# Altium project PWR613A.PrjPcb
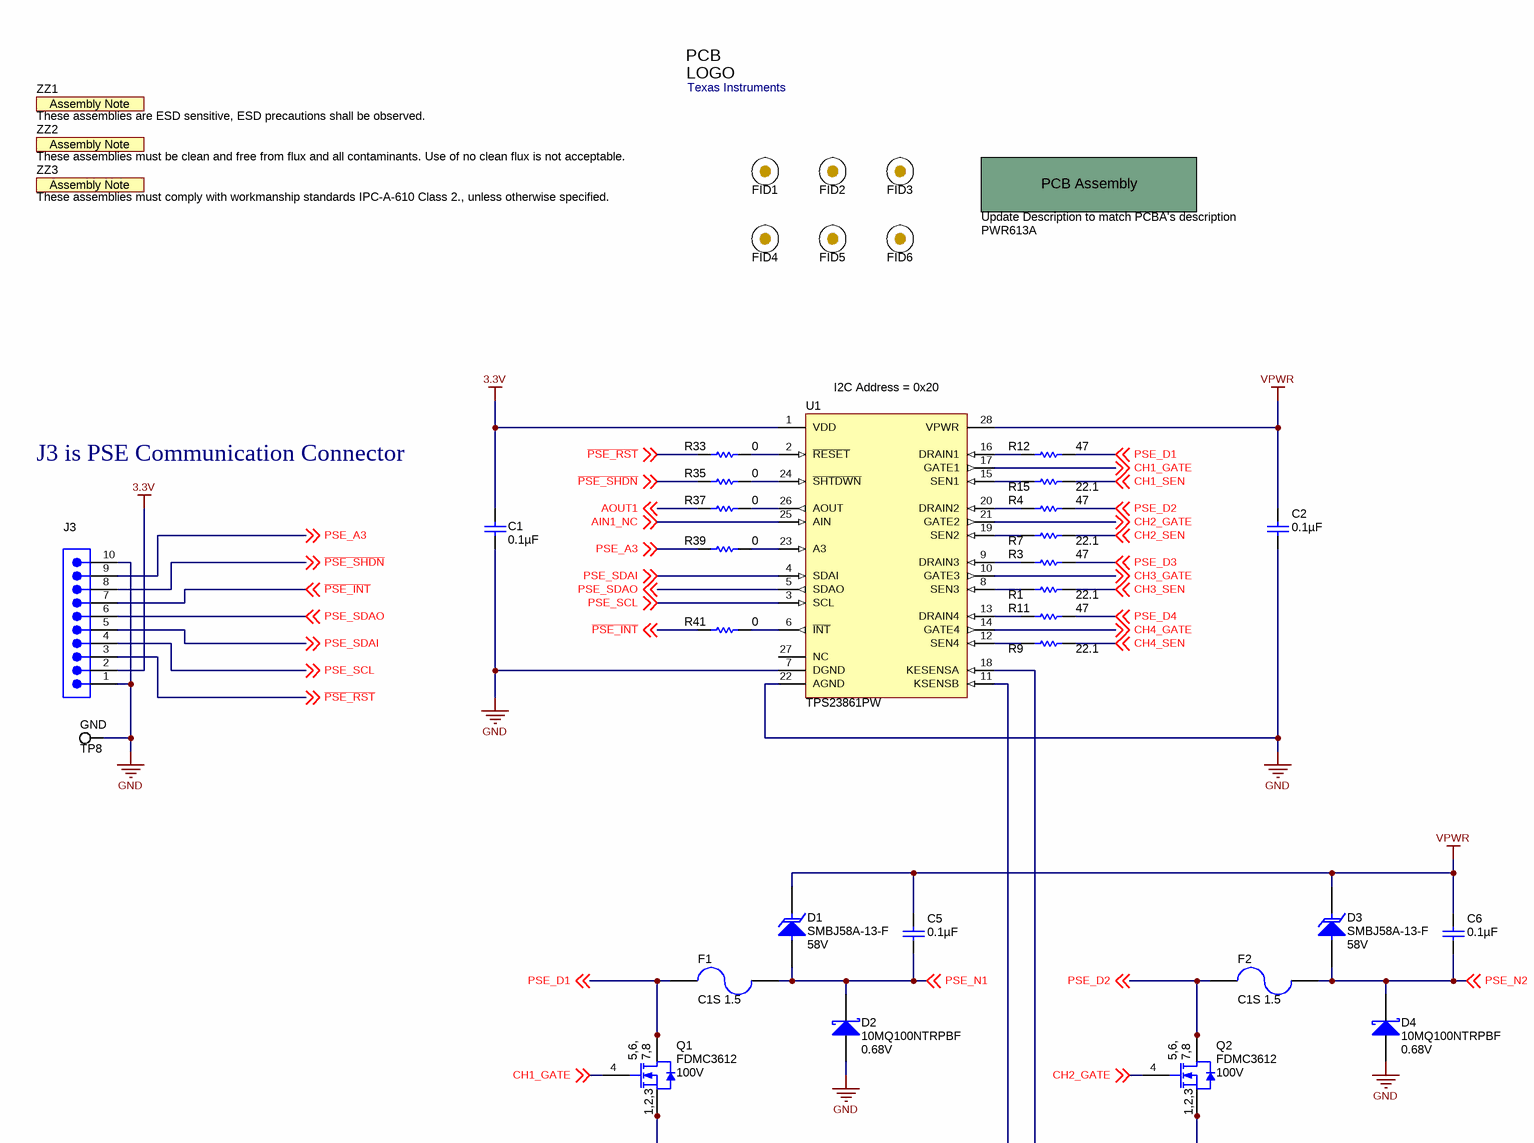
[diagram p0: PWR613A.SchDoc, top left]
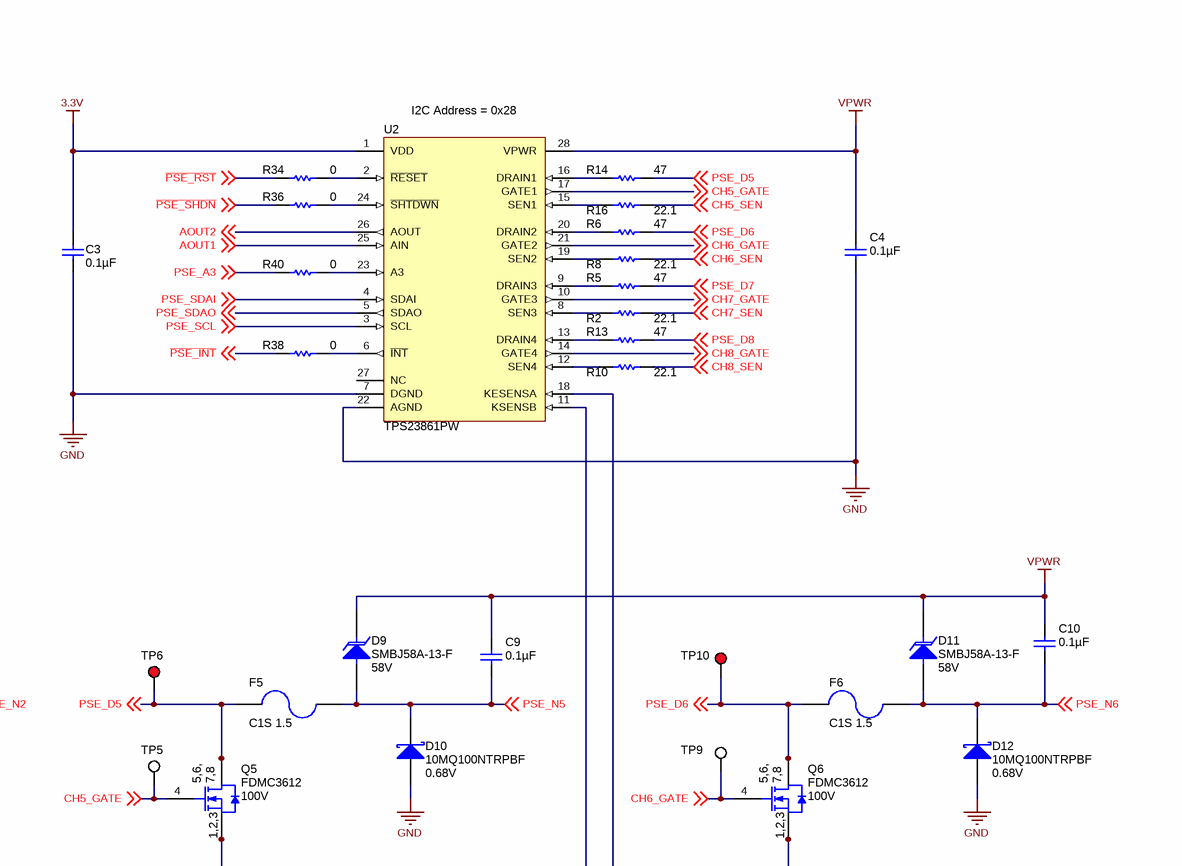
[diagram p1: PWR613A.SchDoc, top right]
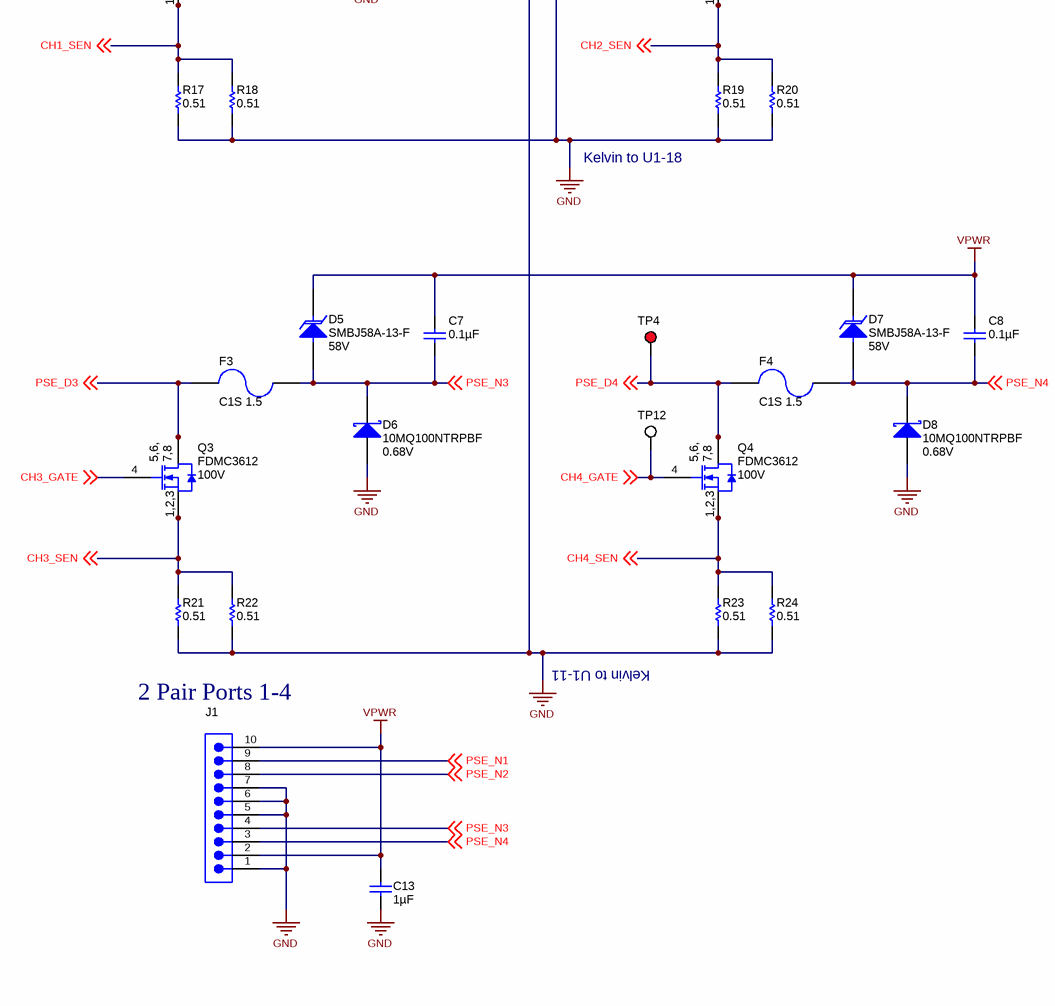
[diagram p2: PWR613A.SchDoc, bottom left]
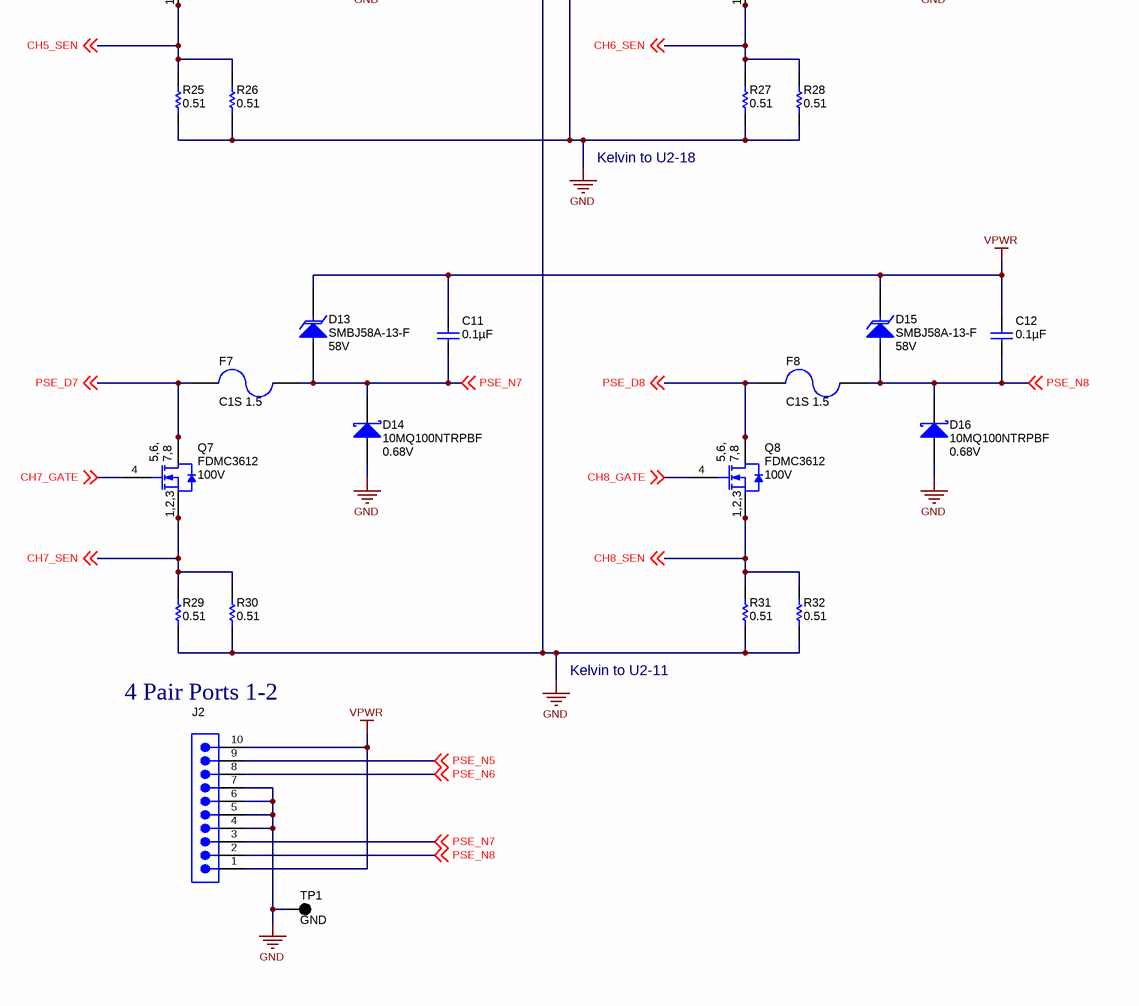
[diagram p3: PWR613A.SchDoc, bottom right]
TechSupport: www.ti.com; SCH_Rev: A; PRJ_Title: TPS23861EVM-613; PRJ_Number: PWR613; PRJ_Engineer: E. Wright; PRJ_Customer: Public Release; PCB_Rev: A; PCB_Layout: E. Wright; CopyrightYear: 2014
1 sheet, 110 parts. Net scope: global (net labels, ports and power ports of the same name join across sheets).
Board file: PWR613A.PcbDoc

## Sheet PWR613A.SchDoc: TPS23861 Daughter Board
size 558 x 431 mm; Engineer: E. Wright; Name: E. Wright

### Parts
!PCBA?  Update Description to match PCBA's description  PartNumber: PWR613A  (mechanical)
C1  ValueDisplayed: 0.1µF  [0603]  (hidden comment: 06035C104KAT2A)
C2  ValueDisplayed: 0.1µF  [0805_HV]  (hidden comment: C2012X7R2A104K)
C3  ValueDisplayed: 0.1µF  [0603]  (hidden comment: 06035C104KAT2A)
C4  ValueDisplayed: 0.1µF  [0805_HV]  (hidden comment: C2012X7R2A104K)
C5  ValueDisplayed: 0.1µF  [0805_HV]  (hidden comment: C2012X7R2A104K)
C6  ValueDisplayed: 0.1µF  [0805_HV]  (hidden comment: C2012X7R2A104K)
C7  ValueDisplayed: 0.1µF  [0805_HV]  (hidden comment: C2012X7R2A104K)
C8  ValueDisplayed: 0.1µF  [0805_HV]  (hidden comment: C2012X7R2A104K)
C9  ValueDisplayed: 0.1µF  [0805_HV]  (hidden comment: C2012X7R2A104K)
C10  ValueDisplayed: 0.1µF  [0805_HV]  (hidden comment: C2012X7R2A104K)
C11  ValueDisplayed: 0.1µF  [0805_HV]  (hidden comment: C2012X7R2A104K)
C12  ValueDisplayed: 0.1µF  [0805_HV]  (hidden comment: C2012X7R2A104K)
C13  ValueDisplayed: 1µF  [1206]  (hidden comment: GRM31CR72A105KA01L)
D1  SMBJ58A-13-F  value 58V  [SMB]
D2  10MQ100NTRPBF  value 0.68V  [SMA]
D3  SMBJ58A-13-F  value 58V  [SMB]
D4  10MQ100NTRPBF  value 0.68V  [SMA]
D5  SMBJ58A-13-F  value 58V  [SMB]
D6  10MQ100NTRPBF  value 0.68V  [SMA]
D7  SMBJ58A-13-F  value 58V  [SMB]
D8  10MQ100NTRPBF  value 0.68V  [SMA]
D9  SMBJ58A-13-F  value 58V  [SMB]
D10  10MQ100NTRPBF  value 0.68V  [SMA]
D11  SMBJ58A-13-F  value 58V  [SMB]
D12  10MQ100NTRPBF  value 0.68V  [SMA]
D13  SMBJ58A-13-F  value 58V  [SMB]
D14  10MQ100NTRPBF  value 0.68V  [SMA]
D15  SMBJ58A-13-F  value 58V  [SMB]
D16  10MQ100NTRPBF  value 0.68V  [SMA]
F1  C1S 1.5  [1206]
F2  C1S 1.5  [1206]
F3  C1S 1.5  [1206]
F4  C1S 1.5  [1206]
F5  C1S 1.5  [1206]
F6  C1S 1.5  [1206]
F7  C1S 1.5  [1206]
F8  C1S 1.5  [1206]
FID1  Fiducial  [Fiducial10-20]  (value not drawn)  (no BOM)
FID2  Fiducial  [Fiducial10-20]  (value not drawn)  (no BOM)
FID3  Fiducial  [Fiducial10-20]  (value not drawn)  (no BOM)
FID4  Fiducial  [Fiducial10-20]  (value not drawn)  (no BOM)
FID5  Fiducial  [Fiducial10-20]  (value not drawn)  (no BOM)
FID6  Fiducial  [Fiducial10-20]  (value not drawn)  (no BOM)
J1  2P4 2P3 2P2 2P1  [TSW-110-07-G-S]  (value not drawn)
J2  Port8&7&6&5  [TSW-110-07-G-S]  (value not drawn)
J3  TSW-110-07-G-S  [TSW-110-07-G-S]  (value not drawn)
Logo1  Texas Instruments  [TI_Symbol_Overlay_Small]  (no BOM)
Q1  FDMC3612  value 100V  [TRANS_Fairchild_MLP08T]
Q2  FDMC3612  value 100V  [TRANS_Fairchild_MLP08T]
Q3  FDMC3612  value 100V  [TRANS_Fairchild_MLP08T]
Q4  FDMC3612  value 100V  [TRANS_Fairchild_MLP08T]
Q5  FDMC3612  value 100V  [TRANS_Fairchild_MLP08T]
Q6  FDMC3612  value 100V  [TRANS_Fairchild_MLP08T]
Q7  FDMC3612  value 100V  [TRANS_Fairchild_MLP08T]
Q8  FDMC3612  value 100V  [TRANS_Fairchild_MLP08T]
R1  value 22.1  [0603]  (hidden comment: CRCW060322R1FKEA)
R2  value 22.1  [0603]  (hidden comment: CRCW060322R1FKEA)
R3  value 47  [0603]  (hidden comment: CRCW060347R0JNEA)
R4  value 47  [0603]  (hidden comment: CRCW060347R0JNEA)
R5  value 47  [0603]  (hidden comment: CRCW060347R0JNEA)
R6  value 47  [0603]  (hidden comment: CRCW060347R0JNEA)
R7  value 22.1  [0603]  (hidden comment: CRCW060322R1FKEA)
R8  value 22.1  [0603]  (hidden comment: CRCW060322R1FKEA)
R9  value 22.1  [0603]  (hidden comment: CRCW060322R1FKEA)
R10  value 22.1  [0603]  (hidden comment: CRCW060322R1FKEA)
R11  value 47  [0603]  (hidden comment: CRCW060347R0JNEA)
R12  value 47  [0603]  (hidden comment: CRCW060347R0JNEA)
R13  value 47  [0603]  (hidden comment: CRCW060347R0JNEA)
R14  value 47  [0603]  (hidden comment: CRCW060347R0JNEA)
R15  value 22.1  [0603]  (hidden comment: CRCW060322R1FKEA)
R16  value 22.1  [0603]  (hidden comment: CRCW060322R1FKEA)
R17  value 0.51  [0805]  (hidden comment: CRM0805-FX-R510ELF)
R18  value 0.51  [0805]  (hidden comment: CRM0805-FX-R510ELF)
R19  value 0.51  [0805]  (hidden comment: CRM0805-FX-R510ELF)
R20  value 0.51  [0805]  (hidden comment: CRM0805-FX-R510ELF)
R21  value 0.51  [0805]  (hidden comment: CRM0805-FX-R510ELF)
R22  value 0.51  [0805]  (hidden comment: CRM0805-FX-R510ELF)
R23  value 0.51  [0805]  (hidden comment: CRM0805-FX-R510ELF)
R24  value 0.51  [0805]  (hidden comment: CRM0805-FX-R510ELF)
R25  value 0.51  [0805]  (hidden comment: CRM0805-FX-R510ELF)
R26  value 0.51  [0805]  (hidden comment: CRM0805-FX-R510ELF)
R27  value 0.51  [0805]  (hidden comment: CRM0805-FX-R510ELF)
R28  value 0.51  [0805]  (hidden comment: CRM0805-FX-R510ELF)
R29  value 0.51  [0805]  (hidden comment: CRM0805-FX-R510ELF)
R30  value 0.51  [0805]  (hidden comment: CRM0805-FX-R510ELF)
R31  value 0.51  [0805]  (hidden comment: CRM0805-FX-R510ELF)
R32  value 0.51  [0805]  (hidden comment: CRM0805-FX-R510ELF)
R33  value 0  [0603]  (hidden comment: CRCW06030000Z0EA)
R34  value 0  [0603]  (hidden comment: CRCW06030000Z0EA)
R35  value 0  [0603]  (hidden comment: CRCW06030000Z0EA)
R36  value 0  [0603]  (hidden comment: CRCW06030000Z0EA)
R37  value 0  [0603]  (hidden comment: CRCW06030000Z0EA)
R38  value 0  [0603]  (hidden comment: CRCW06030000Z0EA)
R39  value 0  [0603]  (hidden comment: CRCW06030000Z0EA)
R40  value 0  [0603]  (hidden comment: CRCW06030000Z0EA)
R41  value 0  [0603]  (hidden comment: CRCW06030000Z0EA)
TP1  GND  [Keystone5011]
TP4  2P4D  [Keystone5000]  (value not drawn)
TP5  4P1AG  [Keystone5002]  (value not drawn)
TP6  4P1AD  [Keystone5000]  (value not drawn)
TP8  GND  [Testpoint_Keystone_Compact]
TP9  4P1BG  [Keystone5002]  (value not drawn)
TP10  4P1BD  [Keystone5000]  (value not drawn)
TP12  2P4G  [Keystone5002]  (value not drawn)
U1  TPS23861PW  [PW0028A_N]
U2  TPS23861PW  [PW0028A_N]
ZZ1  These assemblies are ESD sensitive, ESD precautions shall be observed.  [AssemblyNote]  (no BOM)
ZZ2  These assemblies must be clean and free from flux and all contaminants. Use of no clean flux is not acceptable.  [AssemblyNote]  (no BOM)
ZZ3  These assemblies must comply with workmanship standards IPC-A-610 Class 2., unless otherwise specified.  [AssemblyNote]  (no BOM)

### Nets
3.3V: C1.1 C3.1 J3.2 U1.1(VDD) U2.1(VDD)
GND: C1.2 C2.2 C3.2 C4.2 C13.2 D2.2(A) D4.2(A) D6.2(A) D8.2(A) D10.2(A) D12.2(A) D14.2(A) D16.2(A) J1.1 J1.5 J1.6 J1.7 J2.4 J2.5 J2.6 J2.7 J3.1 J3.10 R17.1 R18.1 R19.1 R20.1 R21.1 R22.1 R23.1 R24.1 R25.1 R26.1 R27.1 R28.1 R29.1 R30.1 R31.1 R32.1 TP1.1 TP8.1 U1.7(DGND) U1.11(KSENSB) U1.18(KESENSA) U1.22(AGND) U2.7(DGND) U2.11(KSENSB) U2.18(KESENSA) U2.22(AGND)
VPWR: C2.1 C4.1 C5.1 C6.1 C7.1 C8.1 C9.1 C10.1 C11.1 C12.1 C13.1 D1.1(K) D3.1(K) D5.1(K) D7.1(K) D9.1(K) D11.1(K) D13.1(K) D15.1(K) J1.2 J1.10 J2.1 J2.10 U1.28(VPWR) U2.28(VPWR)
~{PSE_INT}: J3.7 R38.1 R41.1 ; off-sheet ~{PSE_INT}
~{PSE_RST}: J3.3 R33.1 R34.1 ; off-sheet ~{PSE_RST}
~{PSE_SHDN}: J3.8 R35.1 R36.1 ; off-sheet ~{PSE_SHDN}
AIN1_NC: U1.25(AIN) ; off-sheet AIN1_NC
AOUT1: R37.1 U2.25(AIN) ; off-sheet AOUT1
AOUT2: U2.26(AOUT) ; off-sheet AOUT2
CH1_GATE: Q1.4(G) U1.17(GATE1) ; off-sheet CH1_GATE
CH1_SEN: Q1.1(S) Q1.2(S) Q1.3(S) R15.2 R17.2 R18.2 ; off-sheet CH1_SEN
CH2_GATE: Q2.4(G) U1.21(GATE2) ; off-sheet CH2_GATE
CH2_SEN: Q2.1(S) Q2.2(S) Q2.3(S) R7.2 R19.2 R20.2 ; off-sheet CH2_SEN
CH3_GATE: Q3.4(G) U1.10(GATE3) ; off-sheet CH3_GATE
CH3_SEN: Q3.1(S) Q3.2(S) Q3.3(S) R1.1 R21.2 R22.2 ; off-sheet CH3_SEN
CH4_GATE: Q4.4(G) TP12.1 U1.14(GATE4) ; off-sheet CH4_GATE
CH4_SEN: Q4.1(S) Q4.2(S) Q4.3(S) R9.1 R23.2 R24.2 ; off-sheet CH4_SEN
CH5_GATE: Q5.4(G) TP5.1 U2.17(GATE1) ; off-sheet CH5_GATE
CH5_SEN: Q5.1(S) Q5.2(S) Q5.3(S) R16.2 R25.2 R26.2 ; off-sheet CH5_SEN
CH6_GATE: Q6.4(G) TP9.1 U2.21(GATE2) ; off-sheet CH6_GATE
CH6_SEN: Q6.1(S) Q6.2(S) Q6.3(S) R8.2 R27.2 R28.2 ; off-sheet CH6_SEN
CH7_GATE: Q7.4(G) U2.10(GATE3) ; off-sheet CH7_GATE
CH7_SEN: Q7.1(S) Q7.2(S) Q7.3(S) R2.1 R29.2 R30.2 ; off-sheet CH7_SEN
CH8_GATE: Q8.4(G) U2.14(GATE4) ; off-sheet CH8_GATE
CH8_SEN: Q8.1(S) Q8.2(S) Q8.3(S) R10.1 R31.2 R32.2 ; off-sheet CH8_SEN
PSE_A3: J3.9 R39.1 R40.1 ; off-sheet PSE_A3
PSE_D1: F1.2 Q1.5(D) Q1.6(D) Q1.7(D) Q1.8(D) R12.2 ; off-sheet PSE_D1
PSE_D2: F2.2 Q2.5(D) Q2.6(D) Q2.7(D) Q2.8(D) R4.2 ; off-sheet PSE_D2
PSE_D3: F3.2 Q3.5(D) Q3.6(D) Q3.7(D) Q3.8(D) R3.1 ; off-sheet PSE_D3
PSE_D4: F4.2 Q4.5(D) Q4.6(D) Q4.7(D) Q4.8(D) R11.1 TP4.1 ; off-sheet PSE_D4
PSE_D5: F5.2 Q5.5(D) Q5.6(D) Q5.7(D) Q5.8(D) R14.2 TP6.1 ; off-sheet PSE_D5
PSE_D6: F6.2 Q6.5(D) Q6.6(D) Q6.7(D) Q6.8(D) R6.2 TP10.1 ; off-sheet PSE_D6
PSE_D7: F7.2 Q7.5(D) Q7.6(D) Q7.7(D) Q7.8(D) R5.1 ; off-sheet PSE_D7
PSE_D8: F8.2 Q8.5(D) Q8.6(D) Q8.7(D) Q8.8(D) R13.1 ; off-sheet PSE_D8
PSE_N1: C5.2 D1.2(A) D2.1(K) F1.1 J1.9 ; off-sheet PSE_N1
PSE_N2: C6.2 D3.2(A) D4.1(K) F2.1 J1.8 ; off-sheet PSE_N2
PSE_N3: C7.2 D5.2(A) D6.1(K) F3.1 J1.4 ; off-sheet PSE_N3
PSE_N4: C8.2 D7.2(A) D8.1(K) F4.1 J1.3 ; off-sheet PSE_N4
PSE_N5: C9.2 D9.2(A) D10.1(K) F5.1 J2.9 ; off-sheet PSE_N5
PSE_N6: C10.2 D11.2(A) D12.1(K) F6.1 J2.8 ; off-sheet PSE_N6
PSE_N7: C11.2 D13.2(A) D14.1(K) F7.1 J2.3 ; off-sheet PSE_N7
PSE_N8: C12.2 D15.2(A) D16.1(K) F8.1 J2.2 ; off-sheet PSE_N8
PSE_SCL: J3.4 U1.3(SCL) U2.3(SCL) ; off-sheet PSE_SCL
PSE_SDAI: J3.5 U1.4(SDAI) U2.4(SDAI) ; off-sheet PSE_SDAI
PSE_SDAO: J3.6 U1.5(SDAO) U2.5(SDAO) ; off-sheet PSE_SDAO
NetR1_2: R1.2 U1.8(SEN3)
NetR2_2: R2.2 U2.8(SEN3)
NetR3_2: R3.2 U1.9(DRAIN3)
NetR4_1: R4.1 U1.20(DRAIN2)
NetR5_2: R5.2 U2.9(DRAIN3)
NetR6_1: R6.1 U2.20(DRAIN2)
NetR7_1: R7.1 U1.19(SEN2)
NetR8_1: R8.1 U2.19(SEN2)
NetR9_2: R9.2 U1.12(SEN4)
NetR10_2: R10.2 U2.12(SEN4)
NetR11_2: R11.2 U1.13(DRAIN4)
NetR12_1: R12.1 U1.16(DRAIN1)
NetR13_2: R13.2 U2.13(DRAIN4)
NetR14_1: R14.1 U2.16(DRAIN1)
NetR15_1: R15.1 U1.15(SEN1)
NetR16_1: R16.1 U2.15(SEN1)
NetR33_2: R33.2 U1.2(~{RESET})
NetR34_2: R34.2 U2.2(~{RESET})
NetR35_2: R35.2 U1.24(~{SHTDWN})
NetR36_2: R36.2 U2.24(~{SHTDWN})
NetR37_2: R37.2 U1.26(AOUT)
NetR38_2: R38.2 U2.6(~{INT})
NetR39_2: R39.2 U1.23(A3)
NetR40_2: R40.2 U2.23(A3)
NetR41_2: R41.2 U1.6(~{INT})

Not connected (* = marked no-connect by the designer): U1 27(NC); U2 27(NC)

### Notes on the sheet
- (near U1) I2C Address = 0x20
- (near U2) I2C Address = 0x28
- J3 is PSE Communication Connector
- (near R19) Kelvin to U1-18
- Kelvin to U2-18
- Kelvin to U1-11
- Kelvin to U2-11
- 2 Pair Ports 1-4
- 4 Pair Ports 1-2

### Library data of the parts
!PCBA? = PCBA: Manufacturer: Any; SymbolCreator: a0412235; U/M: EA
C1 C3 = 06035C104KAT2A: CAP, CERM, 0.1uF, 50V, +/-10%, X7R, 0603; Manufacturer: AVX; Polarized: N; CompType: Capacitor; U/M: EA; Cap_F: 0.0000001; Tolerance_%: 10; Value1: Unknown; VDC_V: 50; TaMin_C: -55; TaMax_C: 125
C2 C4-C12 = C2012X7R2A104K: CAP, CERM, 0.1uF, 100V, +/-10%, X7R, 0805; Manufacturer: TDK; Polarized: N; CompType: Capacitor; U/M: EA; Cap_F: 0.0000001; Tolerance_%: 10; ESR_Ohm: 0.0158; Value1: 0.0158 ohm; VDC_V: 100; TaMin_C: -55; TaMax_C: 125; Cap_Case: 0805
C13 = GRM31CR72A105KA01L: CAP, CERM, 1uF, 100V, +/-10%, X7R, 1206; Manufacturer: MuRata; Polarized: N; CompType: Capacitor; U/M: EA; Cap_F: 0.000001; Tolerance_%: 10; Value1: Unknown; VDC_V: 100; TaMin_C: -55; TaMax_C: 125; Cap_Case: 2220
D1 D3 D5 D7 D9 D11 D13 D15 = SMBJ58A-13-F: Diode, TVS, Uni, 58V, 600W, SMB; Manufacturer: Diodes Inc.; U/M: EA; Power_W: 5; Vr_V: 58; Value1: 5W
D2 D4 D6 D8 D10 D12 D14 D16 = 10MQ100NTRPBF: Diode, Schottky, 100V, 1.5A, SMA; Manufacturer: International Rectifier; U/M: EA; Vf_V: 0.68; Io_A: 1.5; Vr_V: 100; TJmax_C: 150
F1-F8 = C1S 1.5: Fuse, 1.5A, 63V, SMD; Manufacturer: Bel Fuse; U/M: EA; OpeningTime_100%_min: 4; OpeningTime_200%_max: 1; VDC_V: 63; Irating_A: 1.5; Rtyp_Ohm: 0.182; MeltingTyp: 0.27; Vdrop: 0.348; Soldering_Wave_MaxTemp_C: 260; Soldering_Wave_MaxTime_s: 6; Soldering_Reflow_MaxTime_s: 40
FID1-FID6 = Fiducial: Fiducial mark.  There is nothing to buy or mount.; SymbolCreator: codlsc
J1-J3 = TSW-110-07-G-S: Header, TH, 100mil, 10x1, Gold plated, 230 mil above insulator; Manufacturer: Samtec, Inc.; SymbolCreator: a0412235; U/M: EA
Logo1 = TI_Logo: Texas Instrument Corporate Signature; SymbolCreator: codlsc
Q1-Q8 = FDMC3612: MOSFET, N-CH, 100V, 3.3A, 3.3x1x3.3mm; Manufacturer: Fairchild Semiconductor; Alternate Manufacturer: None; U/M: EA; ChType: N; VdsMax_V: 100; Value1: 0.11 ohm; Rdson45_Ohm: 0.11; Value2: 21 nC; QgTyp_nC: 21; Vgs_V: 4; IdsMax_A: 3.3
R1 R2 R7-R10 R15 R16 = CRCW060322R1FKEA: RES, 22.1 ohm, 1%, 0.1W, 0603; Manufacturer: Vishay-Dale; CompType: Resistor; Value_Code: 22R1; Tolerance_%: 1; Power_W: 0.1; VDC_V: 75; TempCo: 100 ppm/C; EIA_Code: E96; U/M: EA
R3-R6 R11-R14 = CRCW060347R0JNEA: RES, 47 ohm, 5%, 0.1W, 0603; Manufacturer: Vishay-Dale; CompType: Resistor; Value_Code: 47R0; Tolerance_%: 5; Power_W: 0.1; VDC_V: 75; TempCo: 200 ppm/C; EIA_Code: E24; U/M: EA
R17-R32 = CRM0805-FX-R510ELF: RES, 0.51 ohm, 1%, 0.25W, 0805; Manufacturer: Bourns; CompType: Resistor; Value_Code: R510; Tolerance_%: 1; Power_W: 0.25; VDC_V: 0; TempCo: 100 ppm/C; EIA_Code: E96; U/M: EA
R33-R41 = CRCW06030000Z0EA: RES, 0 ohm, 5%, 0.1W, 0603; Manufacturer: Vishay-Dale; CompType: Resistor; Value_Code: 0000; Tolerance_%: 5; Power_W: 0.1; VDC_V: 75; TempCo: 200 ppm/C; EIA_Code: E24; U/M: EA
TP1 = 5011: Test Point, Multipurpose, Black, TH; Manufacturer: Keystone; CompType: Test Point Loop; U/M: EA
TP4 TP6 TP10 = 5000: Test Point, Miniature, Red, TH; Manufacturer: Keystone; CompType: Test Point Loop; U/M: EA
TP5 TP9 TP12 = 5002: Test Point, Miniature, White, TH; Manufacturer: Keystone; CompType: Test Point Loop; U/M: EA
TP8 = 5016: Test Point, Compact, SMT; Manufacturer: Keystone; CompType: Test Point Loop; U/M: EA
U1 U2 = TPS23861PW: QUAD IEEE 802.3at POWER-OVER-ETHERNET PSE CONTROLLER, PW0028A; Alternate Manufacturer: None; Manufacturer: Texas Instruments; SymbolCreator: a0411947; CompType: IC; U/M: EA
ZZ1-ZZ3 = AssemblyNote: SymbolCreator: codlsc

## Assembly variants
001: not fitted D2 D4 D6 D8 D10 D12 D14 D16 FID1 FID2 FID3 FID4 FID5 FID6 R40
